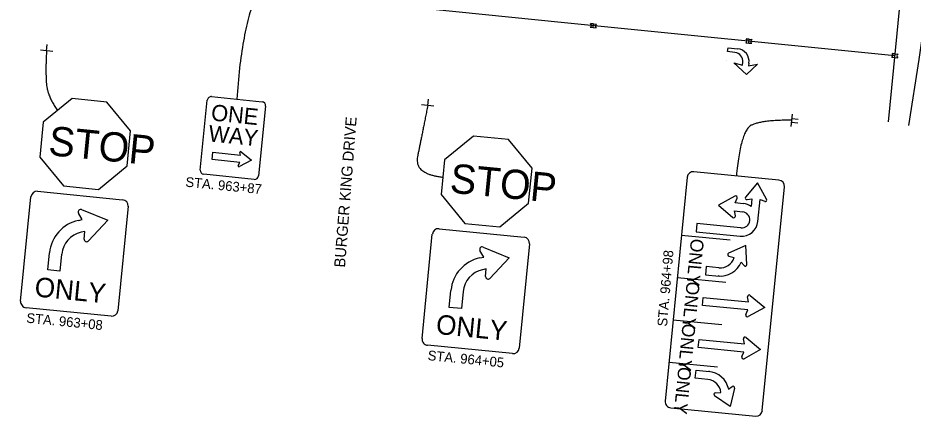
# Model space of a CAD drawing. Extents: x 1847379 to 1850904, y 217032 to 220169.
# Drawn here: x 1850426.1 to 1850655.3, y 218581.8 to 218683.8 of the extents above; entities that cross this region are included whole.
import ezdxf

# ---------------------------------------------------------------- set-up
doc = ezdxf.new("R2010")
doc.units = 0
for name, color, linetype in [('PM_P_Cells', 7, 'Continuous'), ('PM_P_Channelizing_Line', 7, 'Continuous'), ('PM_P_Crosswalk', 7, 'Continuous'), ('PM_P_Stop_Line', 7, 'Continuous'), ('SN_X_Public', 7, 'Continuous'), ('SN_X_Text', 7, 'Continuous')]:
    doc.layers.add(name, color=color, linetype=linetype)

msp = doc.modelspace()

# ---------------------------------------------------------------- linework, layer by layer
at = {"layer": 'PM_P_Cells'}
for p, q in [((1850572.64, 218681.42), (1850573.4, 218681.35)), ((1850572.64, 218681.42), (1850573.4, 218681.35)), ((1850573.49, 218682.32), (1850572.72, 218682.39)), ((1850572.72, 218682.39), (1850573.49, 218682.32)), ((1850573.4, 218681.35), (1850573.49, 218682.32)), ((1850573.4, 218681.35), (1850574.17, 218681.28)), ((1850573.49, 218682.32), (1850574.26, 218682.25)), ((1850612.44, 218677.45), (1850613.21, 218677.38)), ((1850612.44, 218677.45), (1850613.21, 218677.38)), ((1850613.29, 218678.35), (1850612.53, 218678.42)), ((1850612.53, 218678.42), (1850613.29, 218678.35)), ((1850613.21, 218677.38), (1850613.29, 218678.35)), ((1850613.21, 218677.38), (1850613.97, 218677.31)), ((1850613.29, 218678.35), (1850614.06, 218678.28)), ((1850607.82, 218675.2), (1850607.93, 218676.19)), ((1850609.67, 218674.98), (1850607.82, 218675.2)), ((1850607.93, 218676.19), (1850610.39, 218675.91)), ((1850650.7, 218674.62), (1850649.93, 218674.69)), ((1850649.93, 218674.69), (1850650.7, 218674.62)), ((1850650.61, 218673.65), (1850650.7, 218674.62)), ((1850650.7, 218674.62), (1850651.47, 218674.55)), ((1850607.55, 218672.88), (1850607.55, 218672.88)), ((1850612.61, 218669.28), (1850609.42, 218672.33)), ((1850609.42, 218672.33), (1850611.61, 218671.74)), ((1850611.61, 218671.74), (1850611.69, 218672.44)), ((1850613.27, 218672.22), (1850613.2, 218671.56)), ((1850649.84, 218673.72), (1850650.61, 218673.65)), ((1850649.84, 218673.72), (1850650.61, 218673.65)), ((1850650.61, 218673.65), (1850651.38, 218673.58)), ((1850615.5, 218671.97), (1850612.61, 218669.28)), ((1850613.2, 218671.56), (1850615.5, 218671.97)), ((1850615.5, 218671.97), (1850615.5, 218671.97))]:
    msp.add_line(p, q, dxfattribs=at)
for centre, radius, start, end in [((1850572.38, 218681.93), 0.576, 296.8063, 52.8586), ((1850572.38, 218681.93), 0.576, 296.8063, 52.8586), ((1850574.52, 218681.74), 0.576, 116.8063, 232.8586), ((1850612.18, 218677.96), 0.576, 296.8063, 52.8586), ((1850612.18, 218677.96), 0.576, 296.8063, 52.8586), ((1850614.32, 218677.77), 0.576, 116.8063, 232.8586), ((1850609.41, 218672.7), 2.3, 353.453, 83.453), ((1850610.02, 218672.65), 3.28, 352.5446, 83.453), ((1850649.58, 218674.23), 0.576, 296.8063, 52.8586), ((1850649.58, 218674.23), 0.576, 296.8063, 52.8586), ((1850651.73, 218674.04), 0.576, 116.8063, 232.8586)]:
    msp.add_arc(centre, radius, start, end, dxfattribs=at)
at = {"layer": 'PM_P_Channelizing_Line'}
msp.add_lwpolyline([(1850650.65, 218674.09), (1850566.02, 218682.53), (1850518.02, 218687.39), (1850471.03, 218692.07), (1850419.06, 218697.16), (1850371.65, 218702.19), (1850311.6, 218707.75), (1850264.65, 218712.06), (1850215.84, 218717), (1850171.13, 218721.51), (1850121.19, 218725.85), (1850066.37, 218730.8), (1850014.99, 218735.41), (1849965.69, 218739.72), (1849914.21, 218744.36), (1849896.49, 218746.14)], dxfattribs=at)
at = {"layer": 'PM_P_Crosswalk'}
msp.add_lwpolyline([(1850654.2, 218656.28), (1850656.83, 218673.13), (1850658.58, 218685.16), (1850662.02, 218713.29), (1850665.61, 218737.95), (1850667.89, 218757.85)], dxfattribs=at)
at = {"layer": 'PM_P_Stop_Line'}
msp.add_lwpolyline([(1850648.99, 218657.16), (1850651.21, 218679.79), (1850655.22, 218721.21)], dxfattribs=at)
at = {"layer": 'SN_X_Public'}
for p, q in [((1850433.4, 218675.4), (1850433.55, 218676.99)), ((1850434.99, 218675.24), (1850431.81, 218675.56)), ((1850439.92, 218663.14), (1850432.54, 218657.08)), ((1850448.87, 218662.26), (1850439.92, 218663.14)), ((1850475.66, 218663.64), (1850488.6, 218662.33)), ((1850531.02, 218661.37), (1850531.17, 218662.96)), ((1850454.93, 218654.88), (1850448.87, 218662.26)), ((1850472.75, 218644.84), (1850474.57, 218662.75)), ((1850489.49, 218661.23), (1850487.67, 218643.32)), ((1850532.61, 218661.21), (1850529.43, 218661.53)), ((1850624.06, 218655.98), (1850624.39, 218659.17)), ((1850432.54, 218657.08), (1850431.66, 218648.13)), ((1850624.17, 218657.1), (1850625.77, 218656.93)), ((1850624.22, 218657.58), (1850624.22, 218657.58)), ((1850624.27, 218658.05), (1850625.86, 218657.89)), ((1850454.05, 218645.92), (1850454.93, 218654.88)), ((1850542.71, 218653.54), (1850535.33, 218647.49)), ((1850551.67, 218652.66), (1850542.71, 218653.54)), ((1850557.72, 218645.28), (1850551.67, 218652.66)), ((1850475.81, 218647.51), (1850476, 218649.38)), ((1850476, 218649.38), (1850483.07, 218648.67)), ((1850483.06, 218648.65), (1850482.91, 218649.31)), ((1850483.24, 218649.51), (1850485.87, 218647.36)), ((1850431.66, 218648.13), (1850437.71, 218640.75)), ((1850482.86, 218646.8), (1850475.81, 218647.51)), ((1850485.87, 218647.36), (1850482.79, 218645.72)), ((1850535.33, 218647.49), (1850534.45, 218638.53)), ((1850446.67, 218639.86), (1850454.05, 218645.92)), ((1850482.5, 218645.99), (1850482.86, 218646.8)), ((1850556.84, 218636.33), (1850557.72, 218645.28)), ((1850486.57, 218642.43), (1850473.64, 218643.74)), ((1850437.71, 218640.75), (1850446.67, 218639.86)), ((1850615.49, 218641.54), (1850612.43, 218637.87)), ((1850617.78, 218637.34), (1850615.49, 218641.54)), ((1850534.45, 218638.53), (1850540.5, 218631.15)), ((1850609.67, 218638.14), (1850605.44, 218635.8)), ((1850549.46, 218630.27), (1850556.84, 218636.33)), ((1850605.44, 218635.8), (1850609.13, 218632.69)), ((1850609.75, 218636.43), (1850610.26, 218637.61)), ((1850611.82, 218636.22), (1850609.75, 218636.43)), ((1850612.78, 218637.26), (1850614.04, 218637.5)), ((1850614.04, 218637.5), (1850613.84, 218635.46)), ((1850615.56, 218631.67), (1850616.12, 218637.29)), ((1850616.12, 218637.29), (1850617.31, 218636.82)), ((1850442.56, 218632.14), (1850441.6, 218633.82)), ((1850442.38, 218634.71), (1850449.12, 218631.96)), ((1850609.81, 218633.09), (1850609.55, 218634.35)), ((1850609.55, 218634.35), (1850611.62, 218634.15)), ((1850441.59, 218631.93), (1850442.56, 218632.14)), ((1850449.12, 218631.96), (1850444.12, 218626.68)), ((1850540.5, 218631.15), (1850549.46, 218630.27)), ((1850599.96, 218631.11), (1850599.76, 218629.04)), ((1850443.22, 218629.09), (1850442.25, 218628.88)), ((1850443.04, 218627.16), (1850443.22, 218629.09)), ((1850599.76, 218629.04), (1850611.01, 218627.93)), ((1850596.01, 218628.15), (1850608.45, 218626.93)), ((1850545.35, 218622.54), (1850544.39, 218624.23)), ((1850545.17, 218625.11), (1850551.91, 218622.37)), ((1850612.49, 218625.47), (1850608.07, 218623.52)), ((1850612.74, 218620.64), (1850612.49, 218625.47)), ((1850433.73, 218619.24), (1850434.16, 218623.6)), ((1850437.27, 218623.29), (1850436.84, 218618.94)), ((1850544.38, 218622.34), (1850545.35, 218622.54)), ((1850551.91, 218622.37), (1850546.91, 218617.08)), ((1850608.14, 218622.73), (1850609.5, 218622.39)), ((1850546.01, 218619.49), (1850545.04, 218619.28)), ((1850545.84, 218617.57), (1850546.01, 218619.49)), ((1850602.33, 218620.09), (1850602.13, 218618.02)), ((1850605.55, 218619.78), (1850602.33, 218620.09)), ((1850611.28, 218621.19), (1850612.01, 218620.35)), ((1850436.84, 218618.94), (1850433.73, 218619.24)), ((1850594.94, 218617.31), (1850607.38, 218616.09)), ((1850602.13, 218618.02), (1850605.61, 218617.68)), ((1850605.61, 218617.68), (1850605.35, 218617.7)), ((1850536.52, 218609.65), (1850536.95, 218614)), ((1850540.06, 218613.69), (1850539.63, 218609.34)), ((1850613.62, 218612.73), (1850617.31, 218609.62)), ((1850601.35, 218610.14), (1850601.56, 218612.21)), ((1850601.56, 218612.21), (1850613.2, 218611.07)), ((1850613.2, 218611.07), (1850612.94, 218612.33)), ((1850539.63, 218609.34), (1850536.52, 218609.65)), ((1850613, 218608.99), (1850601.35, 218610.14)), ((1850612.49, 218607.81), (1850613, 218608.99)), ((1850617.31, 218609.62), (1850613.08, 218607.28)), ((1850593.87, 218606.48), (1850606.31, 218605.26)), ((1850600.29, 218599.36), (1850600.5, 218601.43)), ((1850600.5, 218601.43), (1850612.14, 218600.29)), ((1850612.14, 218600.29), (1850611.88, 218601.55)), ((1850612.55, 218601.95), (1850616.25, 218598.83)), ((1850611.94, 218598.21), (1850600.29, 218599.36)), ((1850616.25, 218598.83), (1850612.02, 218596.5)), ((1850611.43, 218597.03), (1850611.94, 218598.21)), ((1850592.81, 218595.64), (1850605.25, 218594.42)), ((1850599.52, 218591.48), (1850599.72, 218593.55)), ((1850599.72, 218593.55), (1850603.2, 218593.21)), ((1850603.2, 218593.21), (1850602.94, 218593.24)), ((1850602.73, 218591.16), (1850599.52, 218591.48)), ((1850604.7, 218587.76), (1850606.09, 218587.83)), ((1850608.07, 218588.66), (1850608.95, 218589.34)), ((1850609.61, 218588.91), (1850608.43, 218584.22)), ((1850608.43, 218584.22), (1850604.48, 218587))]:
    msp.add_line(p, q, dxfattribs=at)
for points in [[(1850597.47, 218643), (1850591.82, 218585.64)], [(1850620.95, 218642.26), (1850599.18, 218644.4)], [(1850616.7, 218583.19), (1850622.35, 218640.55)], [(1850426.77, 218611.24), (1850429.4, 218637.98)], [(1850431.11, 218639.39), (1850452.88, 218637.24)], [(1850454.28, 218635.54), (1850451.65, 218608.79)], [(1850611.21, 218630), (1850608.45, 218630.28), (1850599.96, 218631.11)], [(1850533.9, 218629.79), (1850555.67, 218627.65)], [(1850529.56, 218601.64), (1850532.19, 218628.39)], [(1850557.07, 218625.94), (1850554.44, 218599.19)], [(1850449.94, 218607.39), (1850428.17, 218609.53)], [(1850552.73, 218597.79), (1850530.96, 218599.94)], [(1850593.23, 218583.93), (1850615, 218581.79)]]:
    msp.add_lwpolyline(points, dxfattribs=at)
for centre, radius, start, end in [((1850475.56, 218662.65), 1, 84.198, 174.198), ((1850488.49, 218661.33), 1, 354.198, 84.198), ((1850483.11, 218649.35), 0.208, 50.6221, 193.2614), ((1850473.74, 218644.74), 1, 174.198, 264.198), ((1850482.69, 218645.9), 0.208, 156.2746, 297.9235), ((1850486.67, 218643.42), 1, 264.198, 354.198), ((1850599.02, 218642.85), 1.56, 84.3781, 174.3781), ((1850620.79, 218640.7), 1.56, 354.3781, 84.3781), ((1850430.96, 218637.83), 1.56, 84.3781, 174.3781), ((1850609.87, 218637.78), 0.417, 337.0163, 118.8944), ((1850612.71, 218637.63), 0.372, 140.1871, 280.4225), ((1850452.73, 218635.69), 1.56, 354.3781, 84.3781), ((1850611.42, 218632.08), 4.17, 54.3691, 84.3781), ((1850617.45, 218637.16), 0.372, 248.3338, 28.5691), ((1850442.14, 218634.13), 0.625, 67.8128, 209.5846), ((1850611.42, 218632.08), 2.08, 264.3781, 84.3781), ((1850443.59, 218622.67), 9.48, 102.2356, 174.3781), ((1850609.4, 218633.01), 0.417, 229.8619, 5.1455), ((1850609.4, 218633.01), 0.417, 5.1455, 11.74), ((1850611.42, 218632.08), 4.17, 264.3781, 354.3781), ((1850443.59, 218622.67), 6.35, 102.2394, 174.3781), ((1850533.75, 218628.24), 1.56, 84.3781, 174.3781), ((1850443.67, 218627.1), 0.625, 174.8521, 316.6239), ((1850555.52, 218626.09), 1.56, 354.3781, 84.3781), ((1850544.94, 218624.53), 0.625, 67.8128, 209.5846), ((1850546.39, 218613.07), 9.48, 102.2356, 174.3781), ((1850605.92, 218623.51), 3.75, 264.3781, 342.6014), ((1850608.24, 218623.13), 0.417, 113.8854, 255.7635), ((1850605.92, 218623.51), 5.84, 264.3781, 336.6101), ((1850612.32, 218620.62), 0.417, 221.0398, 2.9179), ((1850546.39, 218613.07), 6.35, 102.2394, 174.3781), ((1850546.46, 218617.51), 0.625, 174.8521, 316.6239), ((1850613.35, 218612.41), 0.417, 49.8619, 191.74), ((1850428.32, 218611.09), 1.56, 174.3781, 264.3781), ((1850450.09, 218608.94), 1.56, 264.3781, 354.3781), ((1850612.88, 218607.64), 0.417, 157.0163, 298.8944), ((1850531.12, 218601.49), 1.56, 174.3781, 264.3781), ((1850612.29, 218601.63), 0.417, 49.8619, 191.74), ((1850552.89, 218599.35), 1.56, 264.3781, 354.3781), ((1850611.82, 218596.86), 0.417, 157.0163, 298.8944), ((1850602.37, 218587.43), 5.84, 12.1461, 84.3781), ((1850602.37, 218587.43), 3.75, 6.1549, 84.3781), ((1850604.72, 218587.34), 0.417, 92.9928, 234.8709), ((1850609.21, 218589.01), 0.417, 345.8384, 127.7165), ((1850593.38, 218585.49), 1.56, 174.3781, 264.3781), ((1850615.15, 218583.35), 1.56, 264.3781, 354.3781)]:
    msp.add_arc(centre, radius, start, end, dxfattribs=at)
for points in [[(1850520.37, 218736.61), (1850518.63, 218723.82), (1850505.88, 218701.29), (1850484.26, 218695.43), (1850482.13, 218662.98)], [(1850433.4, 218675.4), (1850433.12, 218670.94), (1850433.55, 218663.71), (1850436.23, 218660.11)], [(1850531.02, 218661.37), (1850529.31, 218652.78), (1850527.49, 218643.82), (1850534.89, 218643.01)], [(1850624.22, 218657.58), (1850616.96, 218657.69), (1850611.11, 218655.11), (1850610.06, 218643.33)]]:
    msp.add_open_spline(points, degree=2, dxfattribs=at)

# ---------------------------------------------------------------- texts
for s, height, rotation, p in [('ONE', 4.172, 354.198, (1850475.39, 218657.56)), ('WAY', 4.172, 354.198, (1850474.72, 218652.21)), ('BURGER KING DRIVE', 2.8, 85.5355, (1850509.82, 218619.79)), ('STOP', 7.5, 354.3781, (1850433.68, 218648.68)), ('STOP', 7.5, 354.3781, (1850536.47, 218639.08)), ('ONLY', 3.333, 264.3781, (1850598.44, 218627.36)), ('ONLY', 5, 354.3781, (1850430.18, 218612.47)), ('ONLY', 3.333, 264.3781, (1850597.36, 218616.37)), ('ONLY', 5, 354.3781, (1850532.97, 218602.88)), ('ONLY', 3.333, 264.3781, (1850596.3, 218605.59)), ('ONLY', 3.333, 264.3781, (1850595.21, 218594.5))]:
    msp.add_text(s, height=height, rotation=rotation, dxfattribs=at).set_placement(p)
at = {"layer": 'SN_X_Text'}
for s, rotation, p in [('STA. 963+87', 354.3781, (1850468.88, 218640.59)), ('STA. 964+98', 85.1482, (1850592.29, 218604.67)), ('STA. 963+08', 354.3781, (1850428.15, 218605.74)), ('STA. 964+05', 354.3781, (1850530.92, 218596.15))]:
    msp.add_text(s, height=2.5, rotation=rotation, dxfattribs=at).set_placement(p)

doc.saveas('drawing.dxf')
